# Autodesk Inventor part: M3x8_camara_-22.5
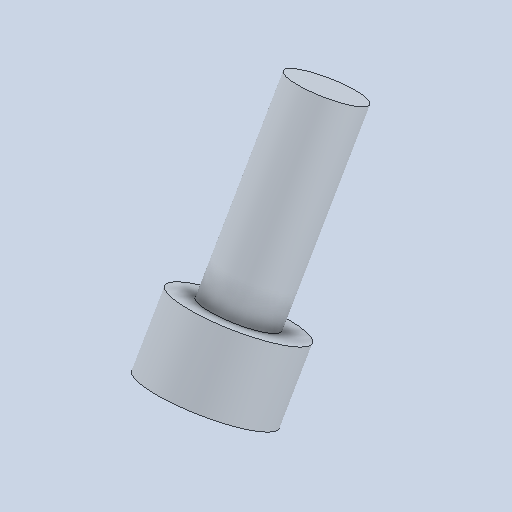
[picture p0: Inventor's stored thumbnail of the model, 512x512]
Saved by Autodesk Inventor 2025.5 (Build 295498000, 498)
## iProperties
Created: 2026-10
Part Number: M3x8_camara_-22.5
Material: Genérico
Document SubType Name: Modeling
Designer: Luis M
Density: 1 g/cm^3
Appearance: Valor por defecto
Author: Luis M
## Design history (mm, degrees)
feature "Base1"
node "Sólido1"
